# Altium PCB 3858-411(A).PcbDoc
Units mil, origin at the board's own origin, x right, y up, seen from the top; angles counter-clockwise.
Board outline 1549 x 1518 mil, 4 copper layers (Top Layer, Internal Plane 1, Mid-Layer 1, Bottom Layer); 62 components, 38 nets, 245 pads, 476 vias.
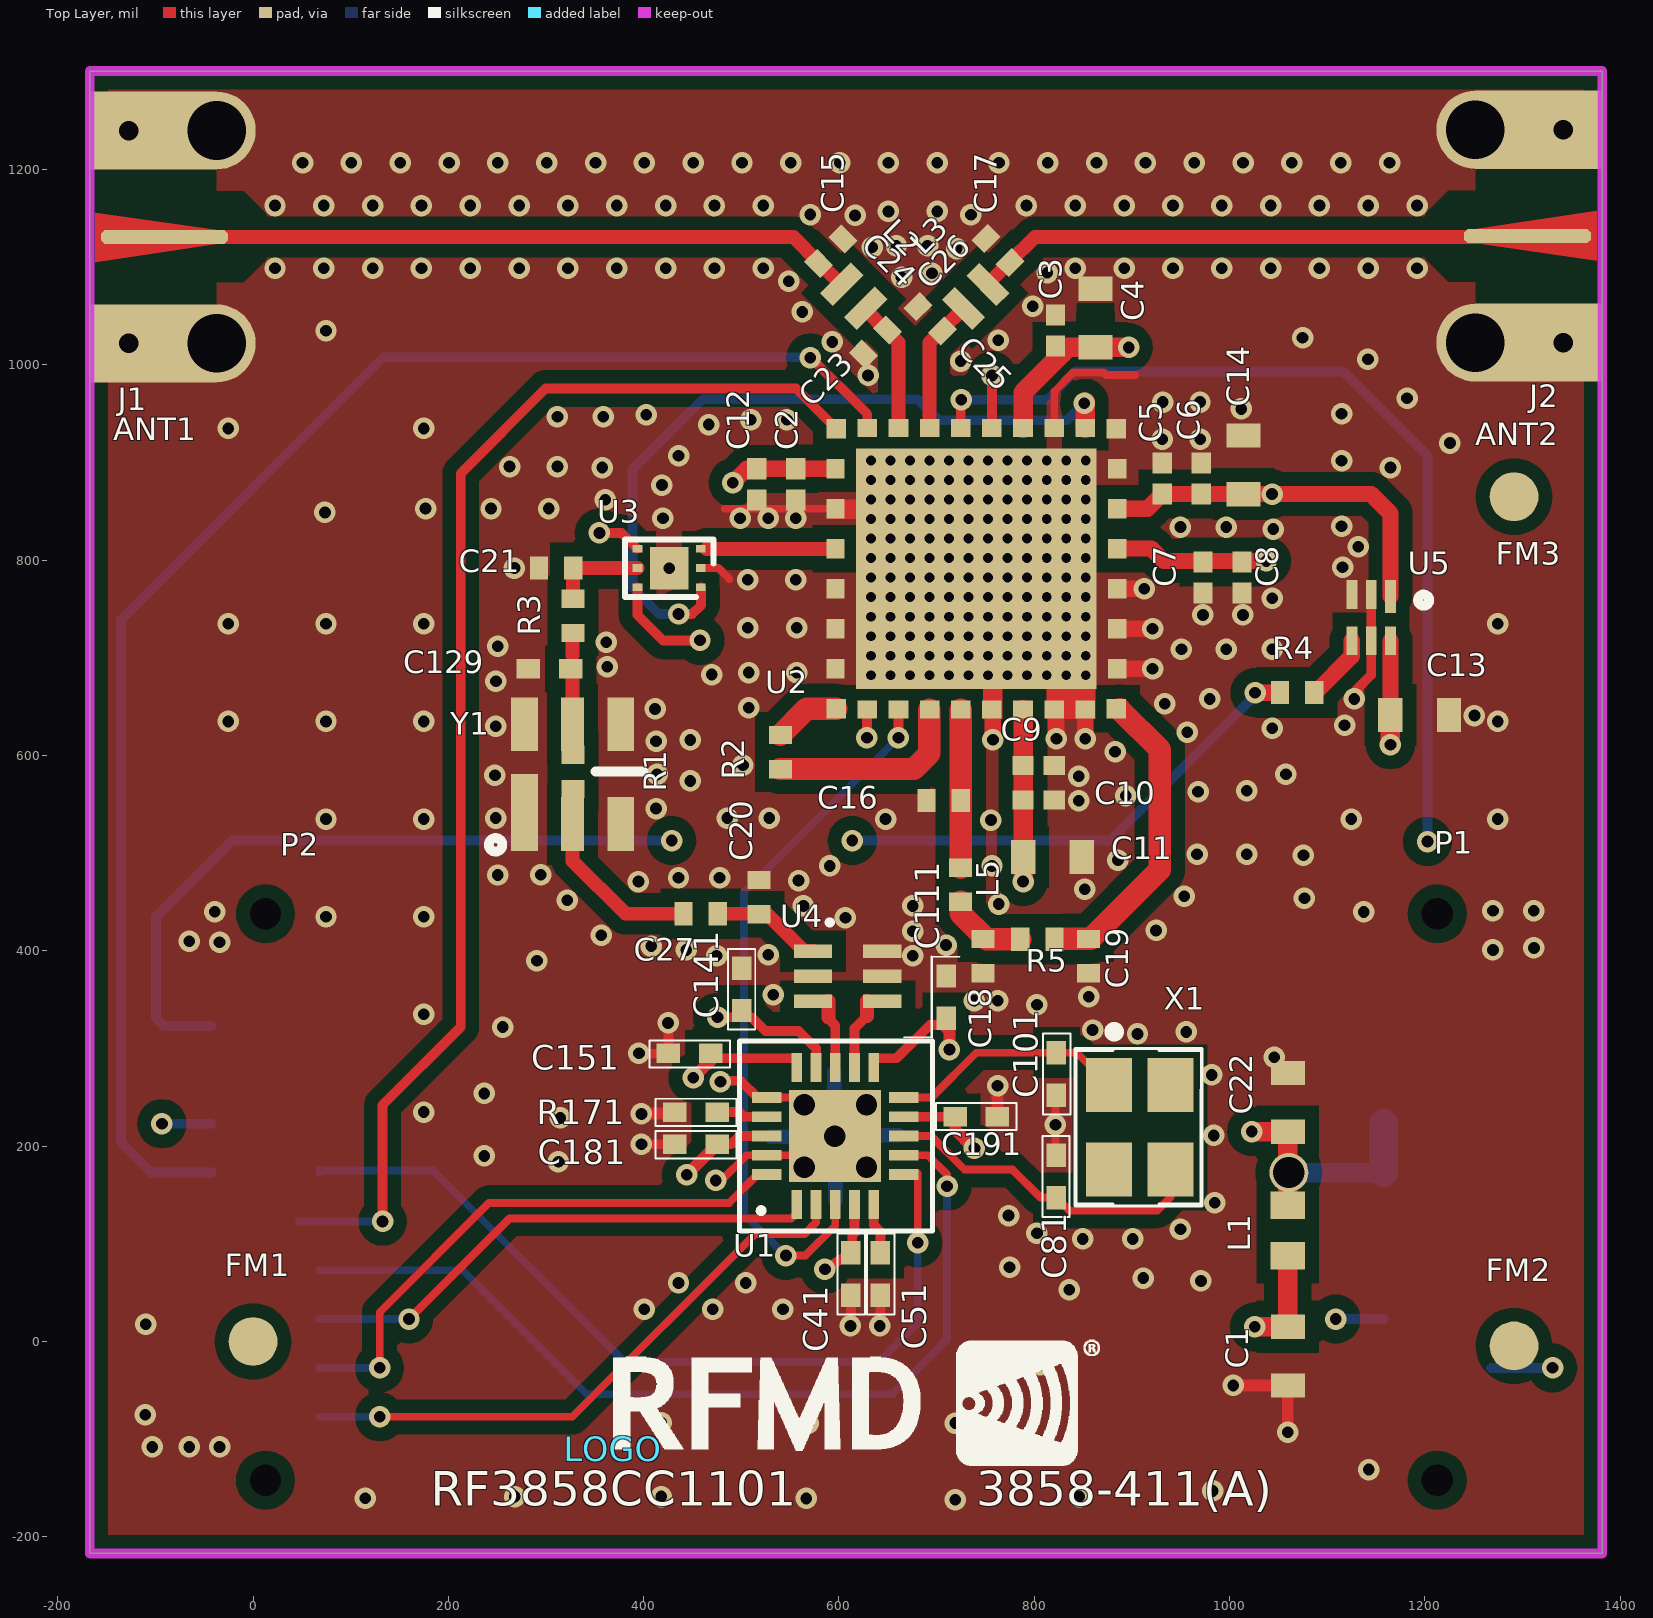
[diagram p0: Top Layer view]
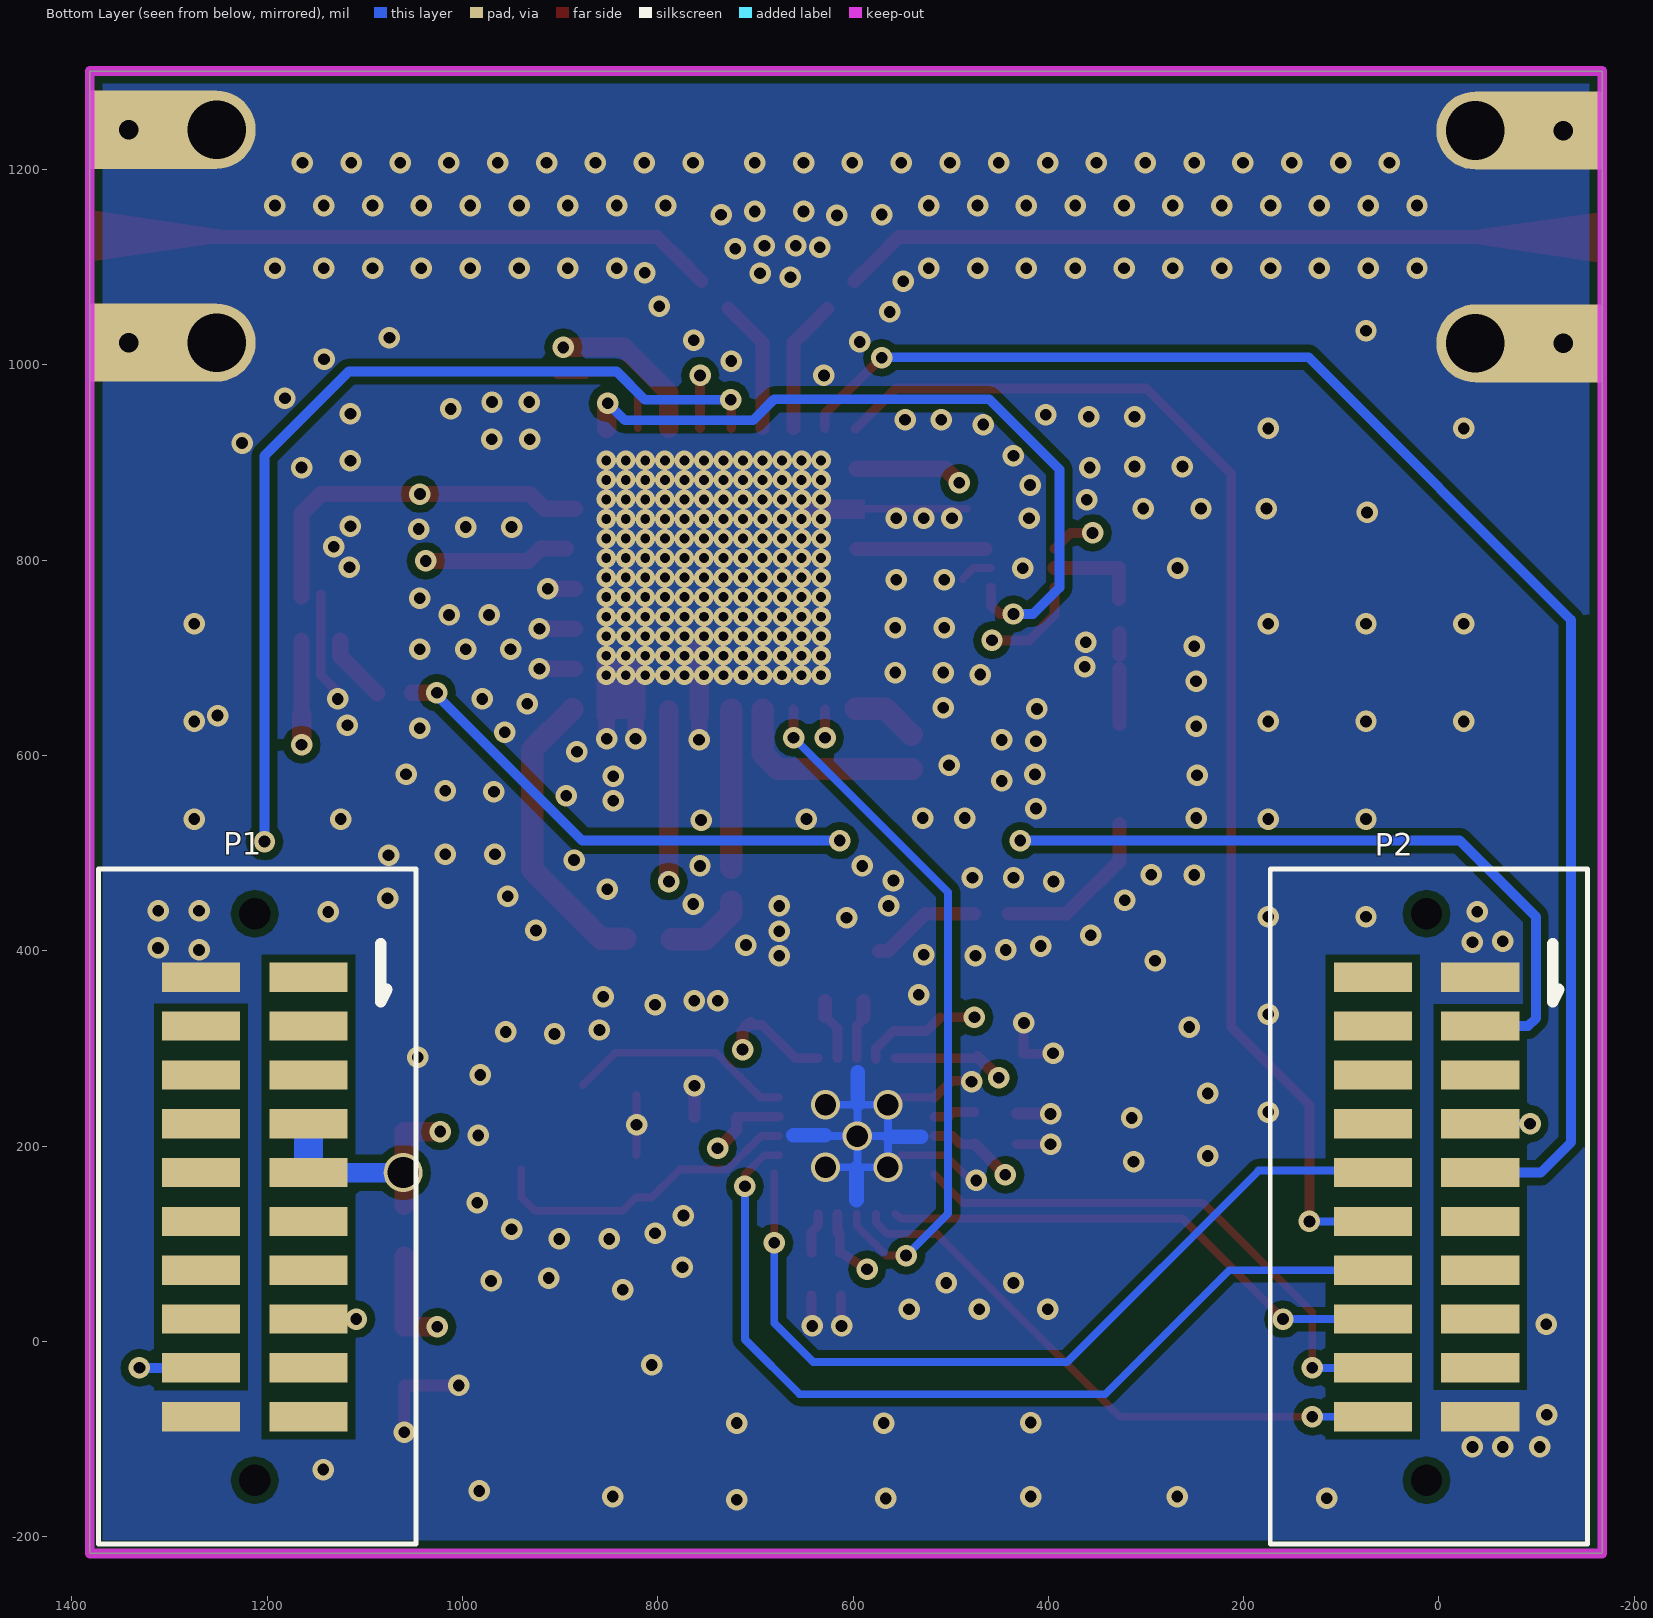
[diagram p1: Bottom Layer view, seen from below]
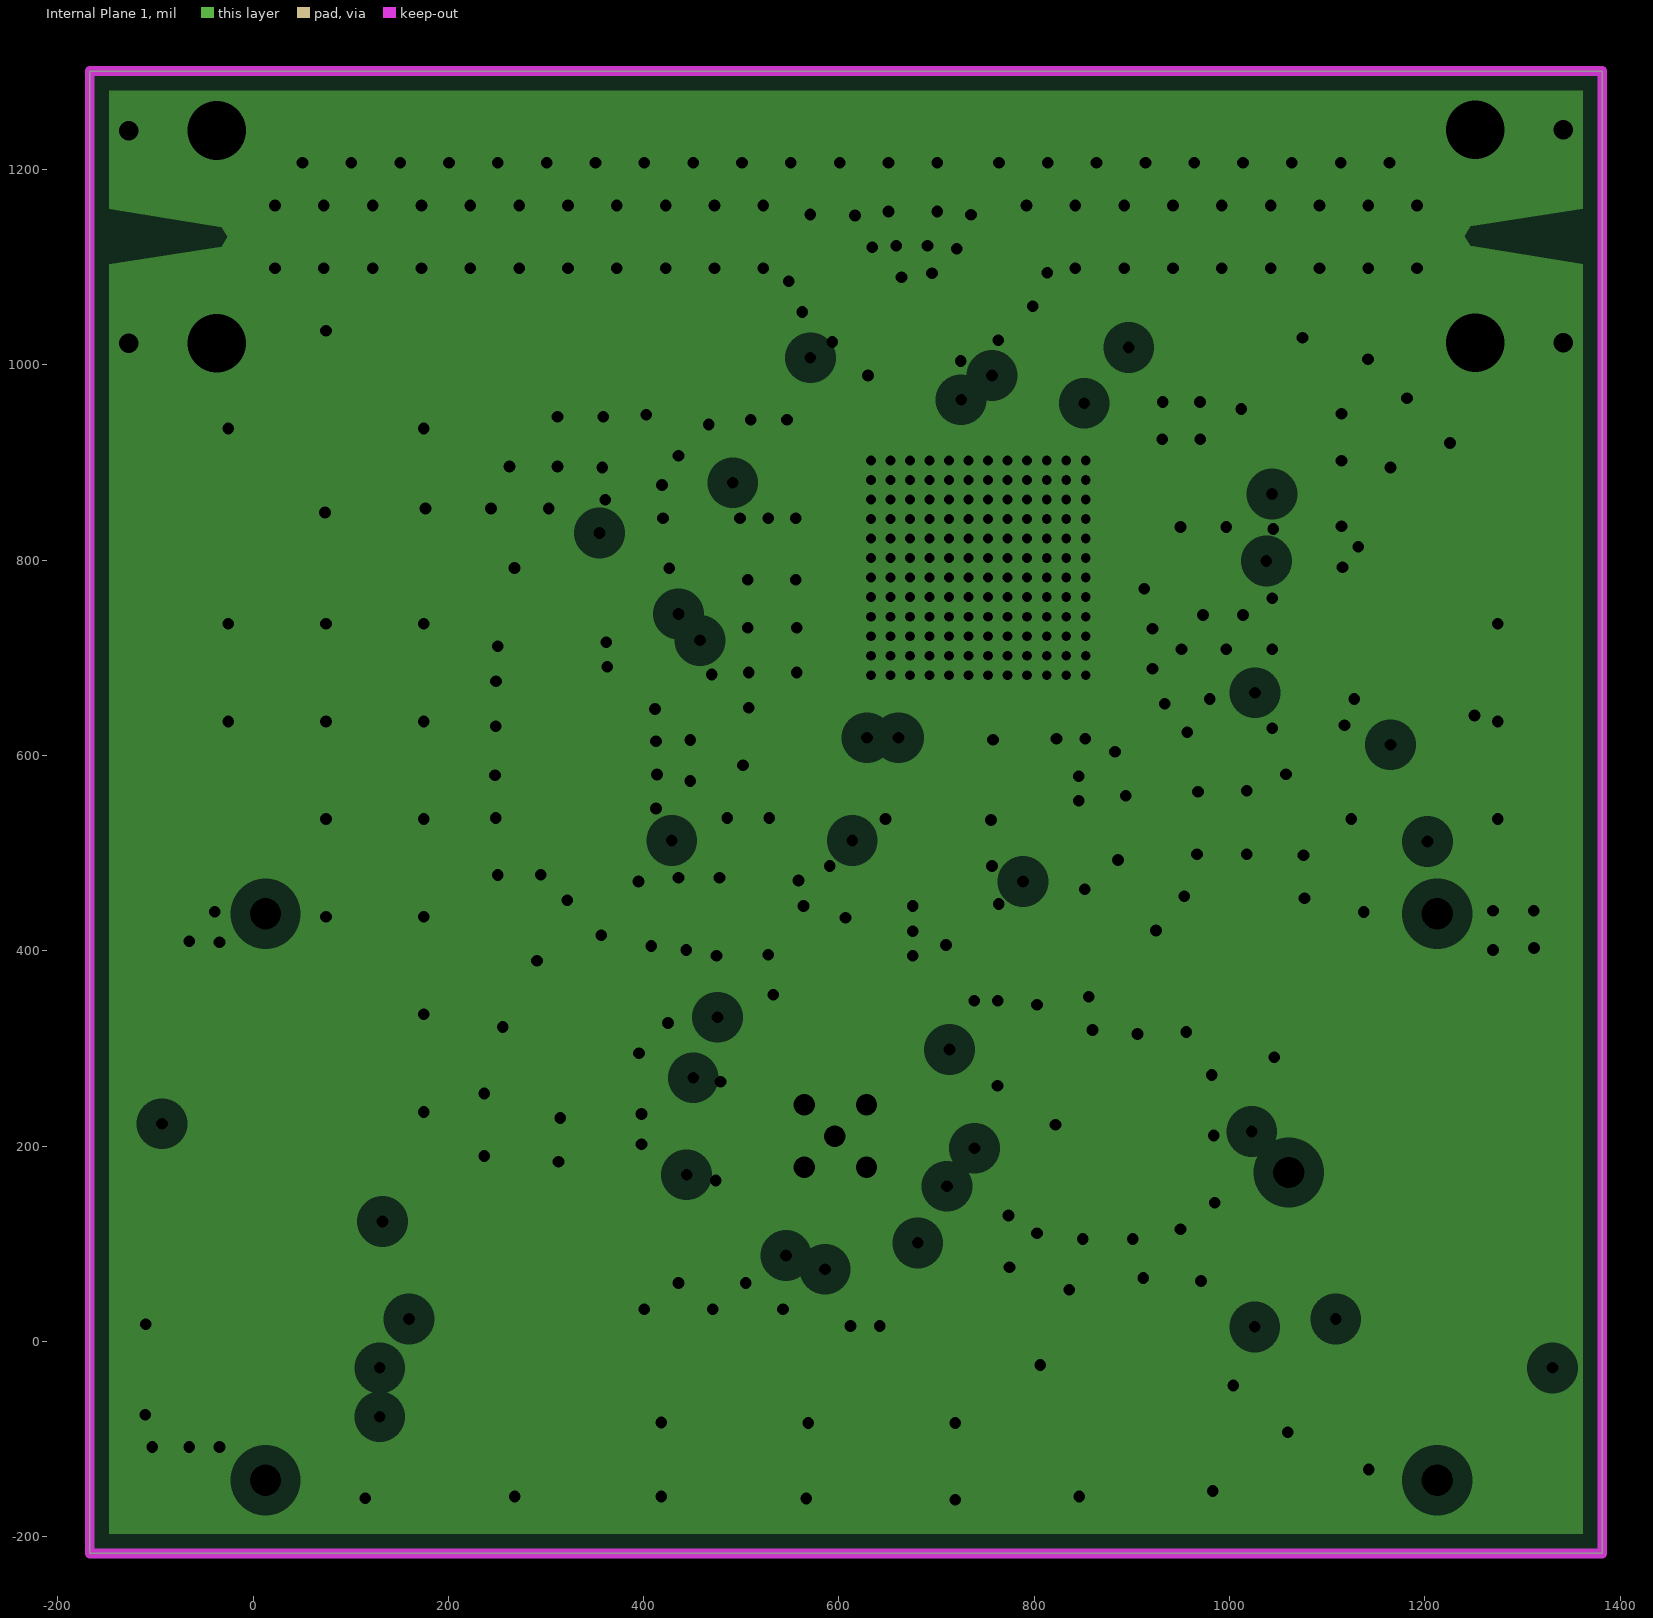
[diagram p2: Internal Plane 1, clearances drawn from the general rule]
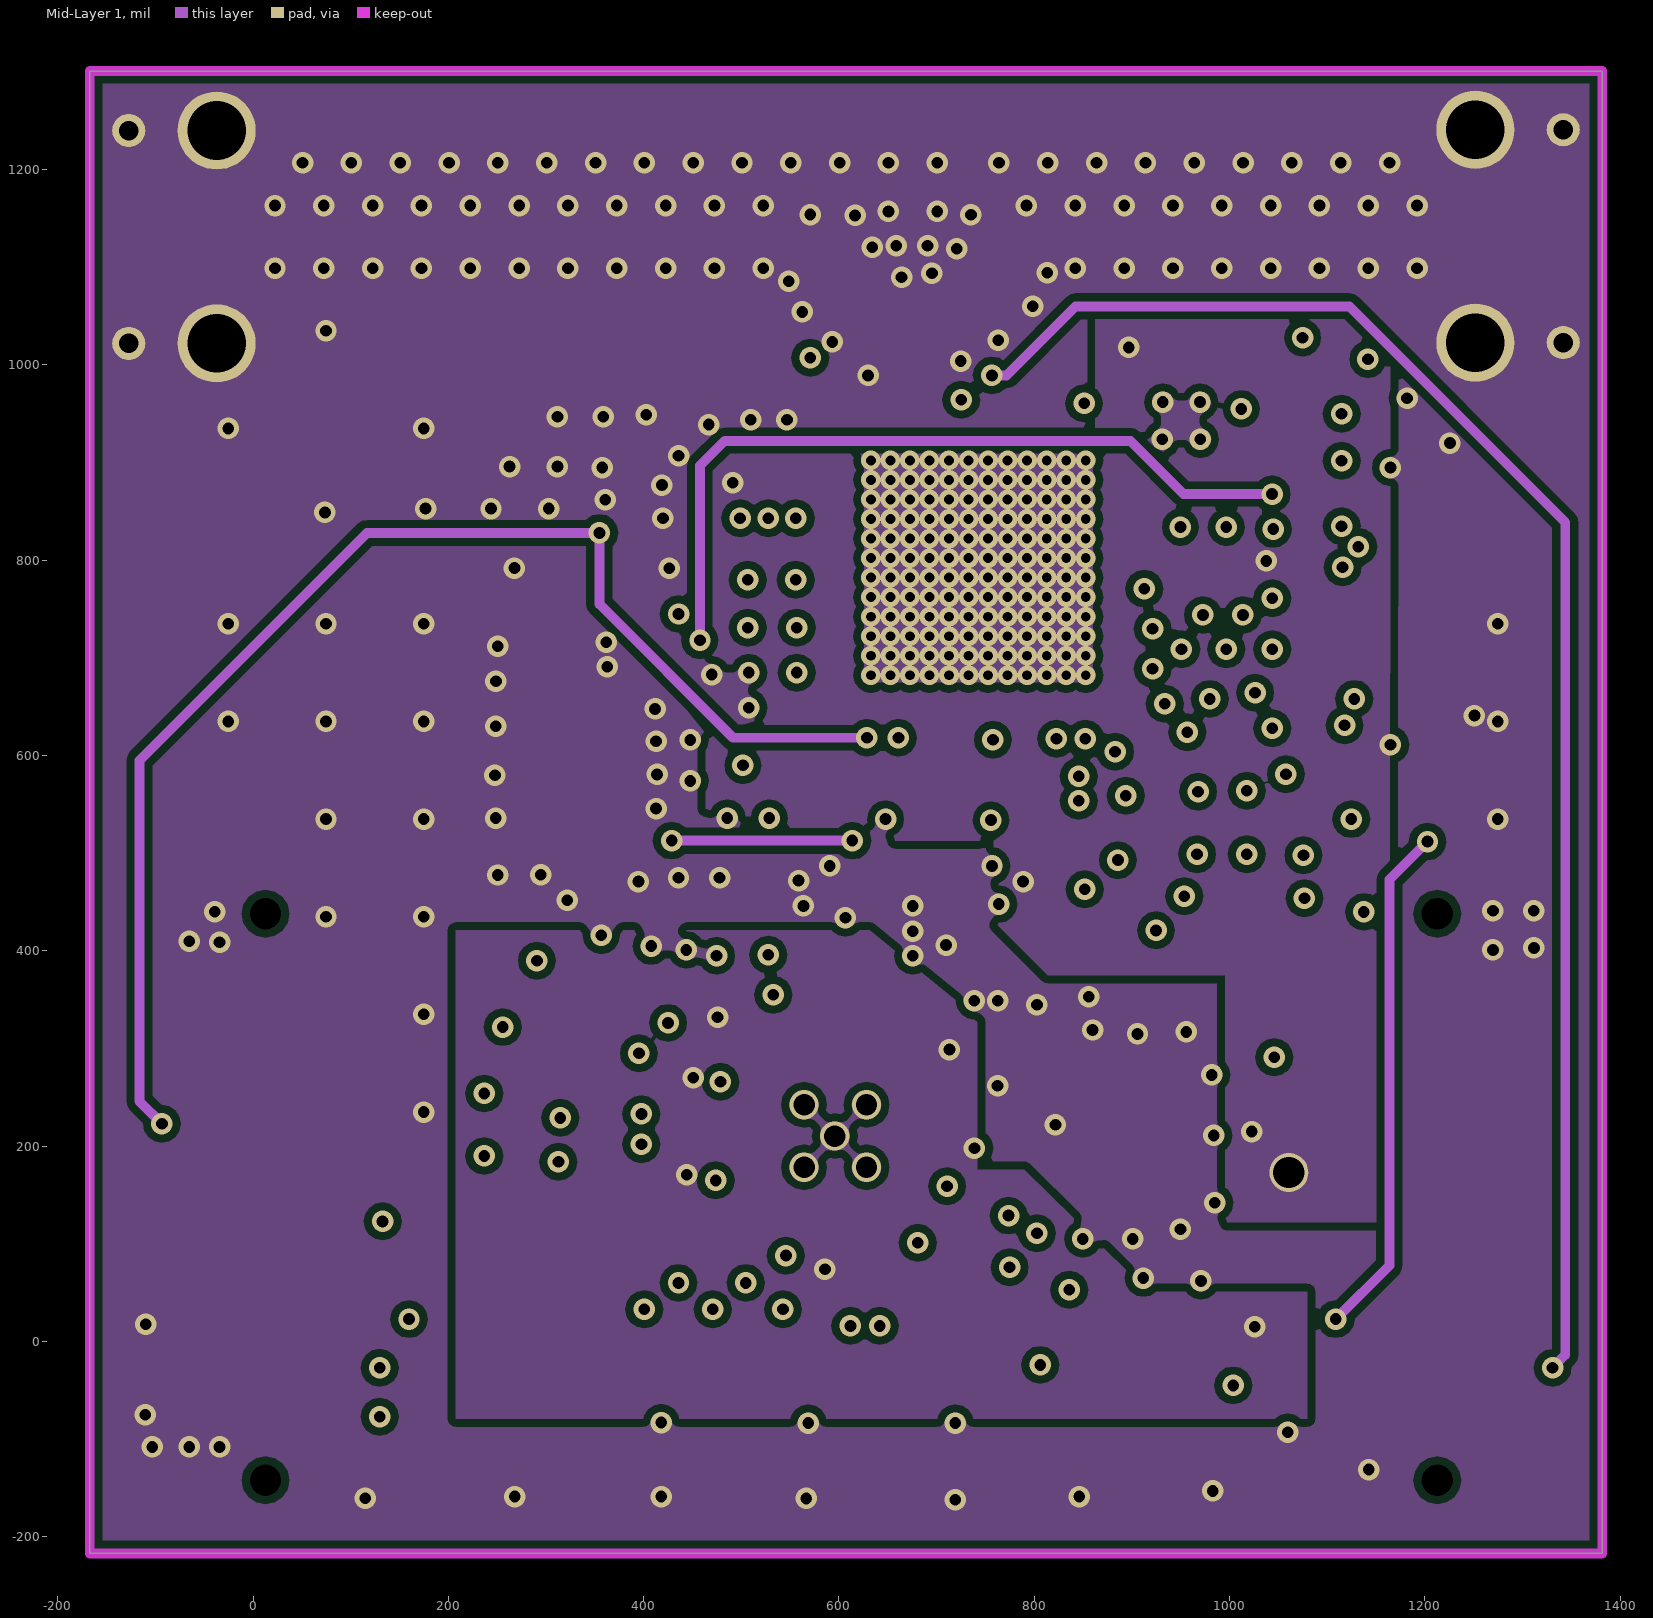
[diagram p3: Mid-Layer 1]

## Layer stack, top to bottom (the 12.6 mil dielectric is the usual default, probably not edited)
Top Layer: signal copper 1.4
Dielectric: core 12.6, FR-4, Dk 4.8
Internal Plane 1: plane copper 1.4, net GND
Dielectric: prepreg 12.6, FR-4, Dk 4.8
Mid-Layer 1: signal copper 1.4
Dielectric: core 12.6, FR-4, Dk 4.8
Bottom Layer: signal copper 1.4

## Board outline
-167.3,-217 1381.7,-217 1381.7,1301 -167.3,1301

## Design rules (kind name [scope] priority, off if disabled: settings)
Clearance Clearance_2 [((InPoly)) And InNet('GND') or (IsVia or IsPad) vs HasFootprintPad('SMA_008_MABDC_GP1_VIPER','1')] p1: gap=40
Clearance Clearance_1 [((InPoly)) AND InNet('GND') and OnLayer('Top Layer')] p2: gap=14
Clearance Clearance_3 [InPoly and (OnLayer('Mid-Layer 1') or OnLayer('Bottom Layer'))] p3: gap=8
Clearance Connectors [IsTrack and IsKeepout vs HasFootprintPad('HDR_*','*') or (HasFootprint('SMA_008_MABDC_GP1_VIPER'))] p4: gap=0
Clearance [InPoly AND InNet('GND') And OnLayer('BottomLayer')] p5: gap=10
Clearance Clearance_4 [All] p6: gap=5
ComponentClearance [All] p1: gap=8 collisioncheckmode=3 verticalgap=10
HoleSize [All] p1: absolutevalues=TRUE maxlimit=125 minlimit=8 maxpercent=80.000 minpercent=20.000
PlaneClearance [All] p1: clearance=20
PlaneConnect [All] p1: planeconnectstyle=Direct reliefexpansion=20 reliefentries=4 reliefconductorwidth=10 reliefairgap=10
PolygonConnect [All] p1: connectstyle=Direct reliefconductorwidth=10 reliefentries=4 polygonreliefangle="90 Angle"
RoutingLayers [All] p1: top layer_v5=TRUE mid layer 1_v5=FALSE bottom layer_v5=TRUE
RoutingVias [All] p1: holewidth=8 width=20 viastyle="Through Hole" minholewidth=8 minwidth=20 maxholewidth=28 maxwidth=50
ShortCircuit [IsKeepOut vs HasFootprintPad('SMA_008_MABDC_G1_VIPER','*') Or HasFootprintPad('HDR_*','*') or (IsPolygon and OnTopLayer)] p1: allowed=TRUE
SolderMaskExpansion [All] p1: expansion=4
TestPointUsage [All] p1: valid=0 allowmultiple=FALSE
Testpoint [(IsPad And (OnTopLayer Or OnBottomLayer))] p1: side=3 testpointundercomponent=TRUE minsize=40 maxsize=100 preferedsize=60 minholesize=20 maxholesize=40 preferedholesize=32 testpointgrid=1 style=297 order=0-112345678
Width [All] p1: maxlimit=100 minlimit=5 preferedwidth=14.25
13 further rules are at their usual default settings.

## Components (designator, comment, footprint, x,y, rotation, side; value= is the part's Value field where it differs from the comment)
C1 "1uF" 0603(A)#1 1059.7,-15 r270 top
C2 "62pF" 0402(A)#1 555.7,877.78 r270 top
C3 "0.1uF" 0402(A)#1 821.8,1035.25 r270 top
C4 "10uF" 0603(A)#2 862.7,1048 r90 top
C5 "62pF" 0402(A)#2 931.03,883.78 r270 top
C6 "DNI" 0402(A)#3 971.03,883.78 r90 top
C7 "68pF" 0402(A)#3 972.67,782.28 r270 top
C8 "0.1uF" 0402(A)#2 1012.67,782.28 r90 top
C9 "68pF" 0402(A)#3 804.45,590 r0 top
C10 "0.1uF" 0402(A)#2 804.45,554.64 r180 top
C11 "10uF" 0603(A)#3 818.5,496 r180 top
C12 "1uF" 0402(A)#1 515.7,877.78 r90 top
C13 "1nF" 0603(A)#2 1194.73,641.6 r180 top
C14 "1uF" 0603(A)#2 1014.38,897.83 r270 top
C15 "3.6pF" 0402_S#1 579.12,1104.43 r45 top
C16 "1.5pF" 0402_S#2 689.83,554.44 r0 top
C17 "3.6pF" 0402_S#1 775.01,1104.61 r135 top
C18 "DNI" 0402_S#2 747.64,411.94 r270 top
C19 "DNI" 0402_S#2 855.82,411.94 r270 top
C20 "DNI" 0402_S#2 517.67,437.73 r90 top
C21 "DNI" 0402_S#2 327.67,791.73 r180 top
C22 "DNI" 0603(A)#1 1059.67,245 r90 top
C23 "3.6pF" 0402_S#1 649.81,1035.39 r225 top
C24 "0.2pF" 0402_S#1 619.85,1050.51 r135 top
C25 "3.6pF" 0402_S#1 705.48,1034.78 r135 top
C26 "0.2pF" 0402_S#1 734.65,1050.98 r45 top
C27 "100pF" 0402_S#2 475.67,437.73 r180 top
C41 "100nF" 0402_TI#1 612.3,90.8 r270 top
C51 "100nF" 0402_TI#1 642.5,90.8 r270 top
C81 "12pF" 0402_TI#1 822.7,147.4 r90 top
C101 "15pF" 0402_TI#1 822.7,295.7 r270 top
C111 "100nF" 0402_TI#1 709.67,331 r90 top
C129 "CAPACITOR(A)" 0402_TI#2 325.3,688.73 r180 top
C141 "100nF" 0402_TI#1 500.67,339 r90 top
C151 "100nF" 0402_TI#1 468.67,295 r180 top
C181 "100nF" 0402_TI#1 475.3,202 r180 top
C191 "100nF" 0402_TI#2 719,230.1 r0 top
FM1 "FM" FM 0,0 r0 top
FM2 "FM" FM 1291.3,-4.5 r90 top
FM3 "FM" FM 1291.3,865.1 r90 top
J1 "ANT1" SMA_008_MABDC_GP1_VIPER -167.3,1131 r0 top locked
J2 "ANT2" SMA_008_MABDC_GP1_VIPER 1381.7,1132 r180 top locked
L1 "1Kohms" 0603_S 1059.7,87.4 r90 top
L2 "6.8nH" 0402_S#1 634.49,1065.29 r135 top
L3 "6.8nH" 0402_S#1 720.39,1065.25 r45 top
L5 "4.7nH (W/W Coilcraft 0402)" 0402_S#2 724.33,450.44 r90 top
LOGO "RFMDLOGO" RFMD_LOGO 368.7,-110 r0 top
P1 "HDR_2X10" 20PIN_CON 1157.7,-77 r0 top
P2 "HDR_2X10" 20PIN_CON -42.3,-77 r0 top
R1 "0ohm" 0402_S#2 327.3,566.01 r90 top
R2 "0ohm" 0402_S#2 539.67,586.28 r90 top
R3 "0ohm" 0402_S#2 327.3,725.73 r90 top
R4 "0ohm" 0402_S#2 1051.86,664.77 r0 top
R5 "0OHM" 0402_S#2 820.48,411.6 r180 top
R171 "56K" 0402_TI#1 475.3,235 r180 top
U1 "CC1101" CC1101 595.8,210.4 r0 top locked
U2 "RF3858" RF3858B 740.67,791.28 r90 top
U3 "RF1126" 1126 426.19,791.87 r180 top
U4 "0896BM15A0001" "JOHANSON 896MHz" 608.87,374.12 r90 top
U5 "2.85V" TPS727XX 1145.04,741.22 r270 top
X1 "26.0MHz (NX3225GA)" Crystal 908.2,219.3 r0 top
Y1 "915.00MHz" "SAW EPCOS B3588" 327.3,581.01 r90 top

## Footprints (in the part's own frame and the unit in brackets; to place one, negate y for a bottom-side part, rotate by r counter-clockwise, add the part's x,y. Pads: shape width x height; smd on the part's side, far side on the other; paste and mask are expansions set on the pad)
20PIN_CON [mil]
  rect 80x30 smd far side paste-40 mask+2: 1(0,450) 2(110,450) 3(0,400) 4(110,400) 5(0,350) 6(110,350) 7(0,300) 8(110,300) 9(0,250) 10(110,250) 11(0,200) 12(110,200) 13(0,150) 14(110,150) 15(0,100) 16(110,100) 17(0,50) 18(110,50) 19(0,0) 20(110,0)
  round 5 hole 32 mask+31.5: 21(55,-65) 22(55,515)
0402(A)#1 [mm]
  rect 0.55x0.5 smd mask+0.074: 1(-0.405,0) 2(0.405,0)
0402(A)#2 [mm]
  rect 0.55x0.5 smd mask+0.051: 1(-0.405,0)
  rect 0.55x0.5 smd mask+0.074: 2(0.405,0)
0402(A)#3 [mm]
  rect 0.55x0.5 smd mask+0.074: 1(-0.405,0)
  rect 0.55x0.5 smd mask+0.051: 2(0.405,0)
0402_S#1 [mm]
  rect 0.475x0.6 smd mask+0.076: 1(-0.004,-0.009) 2(0.885,-0.009)
0402_S#2 [mm]
  rect 0.475x0.6 smd: 1(-0.004,-0.009) 2(0.885,-0.009)
0402_TI#1 [mil]
  rect 24x20 smd paste+0 mask+2: 1(0,0) 2(43.3,0)
0402_TI#2 [mil]
  rect 24x20 smd: 1(0,0) 2(43.3,0)
0603(A)#1 [mil]
  rect 25x35 smd: 1(-30,0) 2(30,0)
0603(A)#2 [mil]
  rect 25x35 smd mask+3: 1(-30,0) 2(30,0)
0603(A)#3 [mil]
  rect 25x35 smd mask+2: 1(-30,0)
  rect 25x35 smd mask+3: 2(30,0)
0603_S [mm]
  rect 0.713x0.9 smd: 1(0.008,0) 2(1.329,0)
1126 [mm] "rev A"
  rect 0.25x0.2 smd: 1(-0.824,0.495) 2(-0.824,-0.005) 3(-0.824,-0.505) 4(0.826,-0.505) 5(0.826,-0.005) 6(0.826,0.495)
  rect 1x1.1 smd: 7(0,0)
  round 0.4 on Top Overlay: ""(-1.257,0.292)
  silkscreen extent -1.15,-0.75 1.15,0.75
CC1101 [mil]
  rect 11x29.99 smd: 1(-39,-70.1) 2(-19.3,-70.1) 3(0.4,-70.1) 4(20,-70.1) 5(39.7,-70.1)
  rect 30x11 smd: 6(70.6,-39.4) 7(70.6,-19.7) 8(70.6,0) 9(70.6,19.7) 10(70.6,39.4)
  rect 11x30 smd: 11(39.7,70.2) 12(20,70.2) 13(0.4,70.2) 14(-19.3,70.2) 15(-39,70.2)
  rect 29.99x11 smd: 16(-69.9,39.4) 17(-69.9,19.7) 18(-69.9,0) 19(-69.9,-19.7) 20(-69.9,-39.4)
  rect 94x94 smd: 21(0,0)
  silkscreen extent -98,-97 100,97
Crystal [mil] "NDK"
  rect 47.2x55.1 smd paste-1.15 mask+3: 1(31.5,-43.3) 2(-31.5,43.3) 3(-31.5,-43.3) 4(31.5,43.3)
  silkscreen extent -66,-80 64,81
FM [mil]
  round 50 smd paste+0 mask+9: 1(0,0)
"JOHANSON 896MHz" [mm]
  rect 0.35x1 smd: 1(0.65,0.9) 2(0,0.9) 3(-0.65,0.9) 4(-0.65,-0.9) 5(0,-0.9) 6(0.65,-0.9)
RF3858B [mm]
  rect 0.51x0.51 smd: 1(-3.64,3.64) 10(-3.64,-3.64) 17(3.64,-3.64) 26(3.64,3.64)
  rect 0.475x0.51 smd: 2(-3.662,2.835) 3(-3.662,2.025) 4(-3.662,1.215) 5(-3.662,0.405) 6(-3.662,-0.405) 7(-3.662,-1.215) 8(-3.662,-2.025) 9(-3.662,-2.835) 18(3.662,-2.835) 19(3.662,-2.025) 20(3.662,-1.215) 21(3.662,-0.405) 22(3.662,0.405) 23(3.662,1.215) 24(3.662,2.025) 25(3.662,2.835)
  rect 0.51x0.475 smd: 11(-2.602,-3.662) 12(-1.561,-3.662) 13(-0.52,-3.662) 14(0.521,-3.662) 15(1.562,-3.662) 16(2.603,-3.662) 27(2.602,3.662) 28(1.561,3.662) 29(0.52,3.662) 30(-0.521,3.662) 31(-1.562,3.662) 32(-2.603,3.663)
  rect 6.25x6.25 smd: 33(0,0)
RFMD_LOGO [mil]
  silkscreen extent 0,-17 499,112
"SAW EPCOS B3588" [mm]
  rect 2x0.7 smd: 1(-1,1.25)
  rect 1.4x0.6 smd: 2(-1.3,0) 5(1.3,0)
  rect 1.4x0.7 smd: 3(-1.3,-1.25) 4(1.3,-1.25) 6(1.3,1.25)
SMA_008_MABDC_GP1_VIPER [mil]
  oct 130x14.25 smd: 1(76.5,0.1)
  rect 130x80 smd: 2(65,109.1) 6(65,-108.9)
  rect 130x80 smd far side: 3(65,109.1) 7(65,-108.9)
  round 34 hole 20: 4(40,109.1) 8(40,-108.9)
  round 80 hole 60: 5(130,109.1) 9(130,-108.9)
  Top Layer pour cut-out: -1.44,-106.8 130,-108.9 130,109.1 -1.44,111.2
  Top Layer region: 132.7,-6.92 132.7,7.08 5.7,25.08 5.7,-25.92 131.7,-6.92
  Internal Plane 1 region: -0.3,-30.92 -0.3,32.08 134.7,10.08 140.7,0.08 134.7,-9.92
TPS727XX [mm] "TI- Linear Regulator"
  rect 0.85x0.28 smd mask+0.05: 1(-0.55,0.5)
  rect 0.75x0.28 smd mask+0.05: 2(-0.6,0) 3(-0.6,-0.5) 4(0.6,-0.5) 5(0.6,0) 6(0.6,0.5)

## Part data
C1 C2 C3 C4 C5 C6 C7 C8 C9 C10 C11 C12 C13 C14 C15 C16 C17 C18 C19 C20 C21 C22 C23 C24 C25 C26 C27 C41 C51 C81 C101 C111 C141 C151 C181 C191: library part CAPACITOR(A), "Capacitor"
C129: "Capacitor"
J1 J2: library part SMA_008, "SMA Connector"
L1 L2 L3 L5 R5: library part INDUCTOR(A), "Inductor"
LOGO: "RFMD LOGO"
R1 R2 R3 R4 R171: library part RESISTOR(A), "Resistor"
U1: library part PKG_20L, "PKG_20L"
U3: library part PKG_6L
U4: library part "BALUN JOHANSON"
U5 Y1: library part "SAW 6L", "SAW FILTER"
X1: library part CRYSTAL(A), "CRYSTAL"

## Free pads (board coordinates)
  round 25 on Top Overlay: 0(591.94,595.28)
  round 40 hole 32 mask-3: 1(1060.7,173)

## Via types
v1: diameter 22, hole 12, Top Layer to Bottom Layer, tented top, 177 vias
v2: diameter 22, hole 12, Top Layer to Bottom Layer, 150 vias
v3: diameter 20, hole 10, Top Layer to Bottom Layer, tented top, 144 vias
v4: diameter 30, hole 22, Top Layer to Bottom Layer, 5 vias

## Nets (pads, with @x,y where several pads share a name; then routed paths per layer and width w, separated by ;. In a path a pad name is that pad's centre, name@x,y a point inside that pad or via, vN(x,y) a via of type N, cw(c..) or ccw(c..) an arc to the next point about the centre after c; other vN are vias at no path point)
CSN: P2.14 U1.7 | length 930.7
  Top Layer w8: U1.7@675.9,190.7 691,190.7 710.7,171 v2(710.7,159)
  Bottom Layer w8: P2.14 214.67,73 341.67,-54 654.67,-54 710.7,2.03 v2(710.7,159)
GDO0: P2.10 U1.6 | length 865.7
  Top Layer w8: v2(680.7,101) U1.6@680.7,172
  Bottom Layer w8: P2.10 67.7,175 184.67,175 380.67,-21 640.67,-21 680.7,19.03 v2(680.7,101)
GND: C1.2 C2.2 C3.1 C4.2 C5.1 C6.2 C7.2 C8.1 C9.2 C10.1 C11.1 C12.1 C13.1 C14.1 C15.2 C16.1 C17.2 C18.2 C19.2 C20.2 C21.2 C22.2 C23.2 C25.2 C41.2 C51.2 C81.2 C101.2 C111.2 C129.2 C141.2 C151.2 C181.2 C191.2 J1.2 J1.3 J1.4 J1.5 J1.6 J1.7 J1.8 J1.9 J2.2 J2.3 J2.4 J2.5 J2.6 J2.7 J2.8 J2.9 P1.2 P1.20 P2.1 P2.19 R171.2 U1.16 U1.19 U1.21 U2.6 U2.8 U2.9 U2.11 U2.12 U2.13 U2.16 U2.17 U2.19 U2.28 U2.30 U2.31 U2.32 U2.33 U3.2 U3.7 U4.2 U4.5 U4.6 U5.2 U5.3 U5.5 Y1.1 Y1.3 Y1.4 Y1.6 | length 1592.4
  Top Layer w8: U3.2 476.63,792.07 487.7,781 ; v2(473.7,165) 479.7,165 505.4,190.7 U1.19 U1.21@550.4,190.7 ; 483.44,852.74 U2.28 ; U1.16@516.5,249.8 U1.16 U1.21@550.4,249.8 ; U2.19 820.39,972.69 839.98,992.28 870.95,992.28 873.65,989.59 903.11,989.59 ; C81.2@821.7,190.7 v2(821.7,222) C101.2@821.7,252.4
  Top Layer w10: v2(397.7,202) C181.2 ; v2@397.97,294.8 425.47,294.8 v2@425.47,322.3 ; v2@424.97,322.3 v2(424.97,326.2) ; v2(478.67,266) 479.67,267 499.3,267 U1.16@516.5,249.8 ; v2@612.3,16 C41.2 ; v2@642.5,16 C51.2 ; v1@1129.7,667 1145.04,682.34 U5.5 U5.2
  Top Layer w12: v2(397.7,233) v2@405.7,233 ; v2@405.7,233.4 R171.2@432,233.4 ; C191.2@762.3,230 v2@762.3,255.2 ; v2@762.4,255.1 v2(762.4,262) ; v2(1003.7,-45) C1.2 v2(1059.7,-93) ; v2@1142.1,-130.6 v2@1144.7,-127.9
  Top Layer w17: v1(757.67,616.28) U2.6@757.67,646.03 ; U2.8 822.67,644.81 v1(822.67,617.28) ; v1(852.28,617.28) U2.9 ; U2.11 v1(921.11,688.84) ; U2.12 v1(921.11,729.83) ; U2.13 v1(912.7,770.81)
  Bottom Layer w8: 595.3,179.4 v4@595.3,210.4 ; v4(595.8,210.4) 627.97,210.4 ; v4(628.2,178.4) 564.22,178.4 564.2,210.4 ; v4(628.2,242.4) 595.3,242.4 ; 564.2,210.4 v4@595.3,210.4 ; 564.2,210.4 v4(564.2,242.4) 595.3,242.4 ; v4@595.3,210.4 595.3,242.4
  Bottom Layer w12: v2@268,-163.1 v2(268,-158.8) ; v2@716.1,-83.3 v2@719.2,-83.3 ; v2@806.44,-23.54 v2@808.3,-25.3 ; v2@846.1,-163.1 v2(846.1,-158.8)
  Bottom Layer w15: 530.3,209.7 562.93,209.7 ; 595.1,243.27 595.1,275.9 ; 596.5,144.9 596.5,177.53 ; 628.67,211.1 661.3,211.1
  other v1: 900.7,105 802.7,111 174.7,235 981.7,273 905.7,315 859.7,319 174.7,335 762.7,349 855.7,353 532.67,355 474.67,395 675.67,395 1269.7,401 1311.7,403 407.67,405 675.67,420 924.67,421 606.67,434 74.7,435 174.7,435 1269.7,441 563.67,446 763.7,448 321.67,452 953.67,456 851.67,463 394.67,471 558.67,472 435.67,475 477.67,475 250.7,477.73 294.67,478 590.67,487 756.7,487 885.67,493 1075.67,498 966.67,499 1017.67,499 755.67,534 74.7,535 174.7,535 647.7,535 1124.7,535 1274.7,535 248.67,536 485.7,536 528.7,536 412.7,545.73 845.53,553.72 893.7,559 967.7,563 1017.7,564 447.7,574 845.53,578.72 247.67,580 413.7,580.73 1057.7,581 501.7,590 882.7,604 412.7,614.73 447.7,616 956.7,624 1043.7,628 248.67,630 1117.7,631 -25.3,635 74.7,635 174.7,635 1274.7,635 1250.7,641 411.7,647.73 507.7,649 933.7,653 979.7,658 1127.7,658 248.7,676 469.7,683 507.7,685 556.7,685 362.7,691 950.7,709 996.7,709 1043.7,709 250.7,712 361.7,716 506.7,731 556.7,731 -25.3,735 74.7,735 174.7,735 1274.7,735 972.7,744 1013.7,744 1043.7,761 506.7,780 555.7,780 267.67,792 426.19,791.87 1115.7,793 1131.7,814 1044.7,832 949.7,834 996.7,834 1114.7,835 419.7,843 498.7,843 527.7,843 555.7,843 73.67,849 176.67,853 243.67,853 302.67,853 360.67,862 418.7,877 357.7,895 1164.7,895 262.7,896 311.7,896 1114.7,902 435.7,907 1225.7,920 931.06,924 970.06,924 -25.3,935 174.7,935 466.7,939 509.7,944 546.7,944 311.7,947 358.7,947 402.7,949 1114.7,950 1012.06,955 931.7,962 969.7,962 1181.7,966 629.8,989.3 724.7,1004 1141.7,1006 593.1,1023.6 763.1,1025.4 1074.7,1028 74.7,1035 562.5,1054.3 798.4,1060.2 664.1,1089.7 695.2,1093.8 720.6,1119 634.1,1120.6 616.49,1153.11 735.19,1153.81
  other v2: 719.2,-162 115,-160.6 566.6,-160.7 418,-158.8 982.7,-153 1142.6,-131.1 -103.3,-108 -65.3,-108 -34.3,-108 568.6,-83.5 719.2,-83.5 418,-83 -110.3,-75 806,-24 611.7,16 641.7,16 -109.9,17.7 400.67,33 470.67,33 542.67,33 835.7,53 435.67,60 504.67,60 970.7,62 911.7,65 774.7,76 849.7,105 949.7,115 773.7,129 984.7,142 312.7,184 236.7,190 983.7,211 314.67,229 236.7,254 1045.7,291 395.17,295.1 955.7,317 255.7,322 802.7,345 738.67,349 290.7,390 527.67,396 443.67,401 709.67,406 -34.3,409 -65.3,410 356.67,416 -39.3,440 1137.5,439.9 1311.6,441.1 675.67,446 1076.7,454 548.6,1085.7 813.4,1094.4 22.48,1098.98 72.48,1098.98 122.48,1098.98 172.48,1098.98 222.48,1098.98 272.48,1098.98 322.48,1098.98 372.48,1098.98 422.48,1098.98 472.48,1098.98 522.48,1098.98 842.02,1098.98 892.02,1098.98 942.02,1098.98 992.02,1098.98 1042.02,1098.98 1092.02,1098.98 1142.02,1098.98 1192.02,1098.98 658.8,1122.1 690.7,1122.1 570.7,1154 650.7,1157.2 700.7,1157.2 22.48,1163.23 72.48,1163.23 122.48,1163.23 172.48,1163.23 222.48,1163.23 272.48,1163.23 322.48,1163.23 372.48,1163.23 422.48,1163.23 472.48,1163.23 522.48,1163.23 792.02,1163.23 842.02,1163.23 892.02,1163.23 942.02,1163.23 992.02,1163.23 1042.02,1163.23 1092.02,1163.23 1142.02,1163.23 1192.02,1163.23 50.7,1207.2 100.7,1207.2 150.7,1207.2 200.7,1207.2 250.7,1207.2 300.7,1207.2 350.7,1207.2 400.7,1207.2 450.7,1207.2 500.7,1207.2 550.7,1207.2 600.7,1207.2 650.7,1207.2 700.7,1207.2 763.8,1207.2 813.8,1207.2 863.8,1207.2 913.8,1207.2 963.8,1207.2 1013.8,1207.2 1063.8,1207.2 1113.8,1207.2 1163.8,1207.2
  other v3: 632.67,682.28 652.67,682.28 672.67,682.28 692.67,682.28 712.67,682.28 732.67,682.28 752.67,682.28 772.67,682.28 792.67,682.28 812.67,682.28 832.67,682.28 852.67,682.28 632.67,702.28 652.67,702.28 672.67,702.28 692.67,702.28 712.67,702.28 732.67,702.28 752.67,702.28 772.67,702.28 792.67,702.28 812.67,702.28 832.67,702.28 852.67,702.28 632.67,722.28 652.67,722.28 672.67,722.28 692.67,722.28 712.67,722.28 732.67,722.28 752.67,722.28 772.67,722.28 792.67,722.28 812.67,722.28 832.67,722.28 852.67,722.28 632.67,742.28 652.67,742.28 672.67,742.28 692.67,742.28 712.67,742.28 732.67,742.28 752.67,742.28 772.67,742.28 792.67,742.28 812.67,742.28 832.67,742.28 852.67,742.28 632.67,762.28 652.67,762.28 672.67,762.28 692.67,762.28 712.67,762.28 732.67,762.28 752.67,762.28 772.67,762.28 792.67,762.28 812.67,762.28 832.67,762.28 852.67,762.28 632.67,782.28 652.67,782.28 672.67,782.28 692.67,782.28 712.67,782.28 732.67,782.28 752.67,782.28 772.67,782.28 792.67,782.28 812.67,782.28 832.67,782.28 852.67,782.28 632.67,802.28 652.67,802.28 672.67,802.28 692.67,802.28 712.67,802.28 732.67,802.28 752.67,802.28 772.67,802.28 792.67,802.28 812.67,802.28 832.67,802.28 852.67,802.28 632.67,822.28 652.67,822.28 672.67,822.28 692.67,822.28 712.67,822.28 732.67,822.28 752.67,822.28 772.67,822.28 792.67,822.28 812.67,822.28 832.67,822.28 852.67,822.28 632.67,842.28 652.67,842.28 672.67,842.28 692.67,842.28 712.67,842.28 732.67,842.28 752.67,842.28 772.67,842.28 792.67,842.28 812.67,842.28 832.67,842.28 852.67,842.28 632.67,862.28 652.67,862.28 672.67,862.28 692.67,862.28 712.67,862.28 732.67,862.28 752.67,862.28 772.67,862.28 792.67,862.28 812.67,862.28 832.67,862.28 852.67,862.28 632.67,882.28 652.67,882.28 672.67,882.28 692.67,882.28 712.67,882.28 732.67,882.28 752.67,882.28 772.67,882.28 792.67,882.28 812.67,882.28 832.67,882.28 852.67,882.28 632.67,902.28 652.67,902.28 672.67,902.28 692.67,902.28 712.67,902.28 732.67,902.28 752.67,902.28 772.67,902.28 792.67,902.28 812.67,902.28 832.67,902.28 852.67,902.28
  other v4: 564.2,178.4
LNA_SEL: U1.3 U2.3 | length 717.9
  Top Layer w8: v1(545.67,88) 565.6,88 596.2,118.6 U1.3@596.2,130.8
  Top Layer w10: v1(660.94,618.27) U2.3
  Bottom Layer w8: v1(545.67,88) 502.67,131 502.67,460 v1(660.94,618.27)
LNA_VREF: P2.7 U2.2 U3.4 | length 1478.2
  Top Layer w10: v1(354.67,828) 377.42,828 U3.4 ; v1(628.69,618.27) U2.2@628.69,647.09
  Mid-Layer 1 w10: v2(-93.3,223) -116.3,246 -116.3,595 116.7,828 v1(354.67,828) 354.67,755.03 491.43,618.27 v1(628.69,618.27)
  Bottom Layer w10: v2(-93.3,223) P2.7
NetC15_1: C15.1 C24.2 J1.1 L2.2 | length 707.5
  Top Layer w14.25: J1.1@-90.52,1131.1 553.23,1131.1 579.75,1104.58 L2.2@598.33,1086
NetC16_2: C16.2 L5.2 U2.5 | length 161.8
  Top Layer w23: L5.2 C16.2 U2.5@724.67,647.03
NetC17_1: C17.1 C26.2 J2.1 L3.2 | length 581.8
  Top Layer w14.25: L3.2@755.43,1085.83 774.85,1105.25 800.7,1131.1 1305.2,1131.1 J2.1@1318.49,1131.1
NetC18_1: C18.1 L5.1 R5.2 | length 83.8
  Top Layer w23: L5.1 724.67,438.42 751.14,411.94 R5.2
NetC19_1: C19.1 R5.1 U2.10 | length 305.8
  Top Layer w23: 833.17,412.6 857.98,412.6 928.67,483.28 928.67,606.09 U2.10@887.48,647.28
NetC20_1: C20.1 C27.1 U4.1 | length 105.9
  Top Layer w14.25: C27.1 C20.1@518.01,438.07 ; C20.1@525.6,438.07 563.96,399.71 U4.1
NetC21_1: C21.1 R3.2 U3.5 | length 97.4
  Top Layer w14.25: R3.2 327.83,760.75 C21.1 U3.5
NetC23_1: C23.1 C24.1 L2.1 U2.24 | length 135.9
  Top Layer w14.25: L2.1@626.64,1057.21 626.71,1057.14 648.89,1034.95 660.94,1022.9 U2.24
NetC25_1: C25.1 C26.1 L3.1 U2.23 | length 136.7
  Top Layer w14.25: U2.23@692.67,935.64 692.67,1023.07 705.18,1035.58 L3.1@727.5,1057.9
NetC27_2: C27.2 R1.1 Y1.2 | length 173.7
  Top Layer w14.25: Y1.2 327.3,491.93 381.16,438.07 C27.2
NetC51_1: C51.1 U1.5 | length 42.9
  Top Layer w10: U1.5@635.6,130.8 635.6,119.1 642.5,112.2 C51.1
NetC81_1: C81.1 U1.8 X1.1 | length 329.3
  Top Layer w8: U1.8@675.9,210.4 694.3,210.4 728.7,176 777.7,176 806.3,147.4 C81.1 836,134 925.7,134 939.7,148 X1.1
NetC101_1: C101.1 U1.10 X1.2 | length 233.5
  Top Layer w8: U1.10@675.9,249.8 694.7,249.8 740.6,295.7 C101.1 843.6,295.7 X1.2
NetC129_1: C129.1 R1.2 R3.1 Y1.5 | length 79.1
  Top Layer w14.25: Y1.5 C129.1@327.3,688.73 ; 327.3,703 R3.1@327.3,725.57
NetP2_3: P2.3 R4.1 | length 1411.9
  Top Layer w16.73: v1(1026.1,664.43) R4.1
  Mid-Layer 1 w10: v1(428.67,513) v2(613.67,513) ; v1@1026.1,661.7 v1(1026.1,664.43)
  Bottom Layer w10: P2.3 -91.3,323 -99.3,331 -99.3,435 -21.3,513 v1(428.67,513) ; v2(613.67,513) 877.4,513 v1@1026.1,661.7
NetR2_1: R2.1 U2.4 | length 204.3
  Top Layer w23: R2.1@539.67,586.28 676.67,586.28 692.67,602.28 U2.4@692.67,646.92
NetR2_2: R2.2 U2.1 | length 68.5
  Top Layer w23: R2.2 566.86,647.98 U2.1
NetR4_2: R4.2 U5.4 | length 85.2
  Top Layer w16.73: R4.2@1087.13,664 1124.93,701.8 ; U5.4@1124.93,717.6 1124.93,701.8 ; U5.4 1125.36,702.23 1124.93,701.8
NetR171_1: R171.1 U1.17 | length 41.9
  Top Layer w10: R171.1 497.5,235 501.7,230.8 ; 502.7,230 U1.17@516.5,230.1
NetU1_12: U1.12 U4.4 | length 63.7
  Top Layer w10: U1.12@615.9,290.1 615.9,320.7 628.6,333.4
  Top Layer w14.25: 628.6,333.4 U4.4@628.6,348.53
NetU1_13: U1.13 U4.3 | length 61.6
  Top Layer w10: 588.39,331.7 596.2,323.8 U1.13@596.2,290.1
  Top Layer w14.25: 589.1,331.7 U4.3@589.1,348.53
NetU2_29: U2.29 U3.3 | length 131.9
  Top Layer w14.25: 464.53,811.75 U2.29
PA_IN: U2.18 U3.1 | length 759
  Top Layer w10: v1(435.7,745) 449.7,745 458.63,753.93 U3.1
  Top Layer w20: U2.18 v1@852.28,961.9
  Bottom Layer w10: v1@435.46,745.24 435.23,745 415.7,745 388.7,772 388.7,893 460.7,965 680.7,965 702.4,943.3 833.68,943.3 v1(851.13,960.75)
PA_VREG: C5.2 C6.1 C14.2 U2.15 U3.6 U5.1 | length 1300
  Top Layer w10: U3.6 393.67,744.03 419.7,718 v1(457.7,718)
  Top Layer w16.73: U2.15 915.98,852.78 C5.2 ; 950.67,867.83 C5.2 ; U5.1 1164.73,847.92 1144.81,867.83 v1(1043.49,867.83) C14.2 C6.1 C5.2
  Mid-Layer 1 w10: v1(457.7,718) 457.7,897 482.98,922.28 898.42,922.28 952.87,867.83 v1(1043.49,867.83)
SCLK: P2.16 U1.1 | length 533.5
  Top Layer w8: v2(159.7,23) 262.7,126 551.1,126 U1.1@556.8,130.8
  Bottom Layer w8: P2.16 v2(159.7,23)
SI: P2.18 U1.20 | length 566.4
  Top Layer w8: v2@127.7,-27 v2(129.7,-27) 129.7,30.03 241.67,142 487.7,142 ; 487.6,142.1 U1.20@516.5,171.1
  Bottom Layer w8: P2.18 v2(129.7,-27)
SO: P2.20 U1.2 | length 602.1
  Top Layer w8: v2@131.7,-77 v2(129.7,-77) 326.95,-77 513.95,110 564.7,110 576.5,121.9 U1.2@576.5,130.8
  Bottom Layer w8: P2.20 v2(129.7,-77)
VDD: C1.1 C41.1 C111.1 C141.1 C151.1 C181.1 C191.1 L1.1 U1.4 U1.9 U1.11 U1.14 U1.15 U1.18 | length 702
  Top Layer w10: C151.1@470.8,290.1 471.1,290.1 U1.15@556.8,290.1 ; C181.1 489.7,202 498.1,210.4 U1.18@516.5,210.4 ; v2(475.67,332) C141.1@500.67,332 ; 510.67,332 524.67,318 558.7,318 576.7,300 U1.14@576.7,289.2 ; v2(585.67,74) C41.1 ; C41.1@613.7,90.8 613.7,111 615.9,111 U1.4@615.9,130.8 ; U1.11@635.6,290.1 659.1,290.1 693.19,324.04 707.39,324.01 709.65,324 C111.1@710.67,324 ; U1.9@675.9,230.1 C191.1
  Top Layer w12: v2(443.98,170.68) C181.1 ; v2(450.67,270) 463.7,283 ; 464,283 471.1,290.1 C151.1@472.33,291.33 ; C111.1@705.03,326.37 707.39,324.01 713.1,318.3 v2(713.1,299) ; C191.1@719,229 719,216.7 v2@737.7,198
  Top Layer w20: v2(1025.67,15) C1.1 L1.1@1059.7,87.4
  other v2: 738.7,198
VDDRF: C2.1 C3.2 C4.1 C7.1 C8.2 C9.1 C10.2 C11.2 C12.2 C13.2 C22.1 L1.2 P1.7 P1.9 pad.1 U2.7 U2.14 U2.20 U2.27 U5.6 | length 969.3
  Top Layer w16.73: v1(491.33,879.5) 491.2,879.5 491.27,879.57 505.42,893.72 C12.2 ; C12.2@513.7,893.72 C12.2 ; U2.27 C2.1 C12.2 ; U2.14@893.85,812.13 919.91,812.13 932.71,799.33 972.67,799.33 1012.67,799.33 v1(1037.67,799.33) ; C13.2 U5.6
  Top Layer w20: v1(788.5,471) C11.2 C10.2 C9.1 U2.7 ; U2.20 788.5,971.8 828.9,1012.2 834.7,1018 C4.1 v1(896.67,1018) ; v1(1022.67,215) C22.1 ; L1.2 1059.7,173 C22.1 ; v1(1164.73,611.08) C13.2
  Bottom Layer w20: v1(788.5,471) v1@789.5,472 ; pad.1 P1.9
  Bottom Layer w30: P1.9 P1.7
VRX1: P2.9 U2.25 | length 1554.9
  Top Layer w10: v1@571.01,1007.69 629.05,949.65 U2.25
  Bottom Layer w10: P2.9 -104.3,173 -135.3,204 -135.3,739 133.69,1007.99 570.71,1007.99 v1@571.01,1007.69
  other v1: 570.71,1007.39
VRX2: P2.12 U2.26 | length 1322.5
  Top Layer w10: v1(132.67,123) 132.67,242 212.7,322.03 212.7,889 299.7,976 555.95,976 U2.26
  Bottom Layer w8: P2.12@47.14,123 P2.12 v1(132.67,123)
VTX1: P1.15 U2.22 | length 1526.1
  Top Layer w10: U2.22 v1@724.72,964.3
  Mid-Layer 1 w10: v2(1108.7,23) 1163.67,77.97 1163.67,473 v2(1202.67,512)
  Bottom Layer w10: v1(725.09,964.3) 813,964.3 841.98,993.28 1116.42,993.28 1202.67,907.03 v2(1202.67,512) ; v2(1108.7,23) P1.15
VTX2: P1.18 U2.21 | length 1697.7
  Top Layer w10: U2.21 v1(756.61,989.28) v1@756.61,991.28
  Mid-Layer 1 w10: v1@756.98,989.28 771.48,989.28 842.2,1060 1122.7,1060 1343.7,839 1343.7,-14 v2(1330.7,-27)
  Bottom Layer w10: P1.18 v2(1330.7,-27)
pads on no net: FM1.1 FM2.1 FM3.1 P1.1 P1.3 P1.4 P1.5 P1.6 P1.8 P1.10 P1.11 P1.12 P1.13 P1.14 P1.16 P1.17 P1.19 P1.21 P1.22 P2.2 P2.4 P2.5 P2.6 P2.8 P2.11 P2.13 P2.15 P2.17 P2.21 P2.22 U3. X1.3 X1.4

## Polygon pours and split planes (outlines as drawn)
GND on Top Layer "Top Layer-No Net" (solid, remove dead copper, pour order 1000): -167.3,-217 1381.7,-217 1381.7,1301 -167.3,1301
VDD on Mid-Layer 1 "Mid-Layer 1-No Net" (solid, pour order 1000): 207.67,-79 207.67,421 631.67,421 741.67,331 741.67,176 789.67,176 916.3,51 1079.67,51 1079.67,-79
VDDRF on Mid-Layer 1 "Mid-Layer 1-No Net 1" (solid, pour order 1001): 1163.67,122 995.67,122 995.67,375 813.67,375 758.67,430 758.67,513 463.67,513 462.67,898 502.67,935 862.67,935 862.67,1050 1164.67,1050
GND on Mid-Layer 1 "Mid-Layer 1-No Net 2" (solid, remove dead copper, pour order 1002): -167.3,-217 -167.3,1301 1381.7,1301 1381.7,-217
GND on Bottom Layer "BottomLayer-GND" (solid, remove dead copper, pour order 1007): -167.3,-217 -167.3,1301 1381.7,1301 1381.7,-217
no net on Top Overlay (solid): 523.2,134.1 523.19,133.89 523.17,133.68 523.13,133.48 523.08,133.27 523.02,133.07 522.94,132.88 522.85,132.69 522.74,132.51 522.63,132.34 522.5,132.17 522.36,132.02 522.21,131.87 522.05,131.74 521.88,131.61 521.7,131.5 521.52,131.4 521.32,131.32 521.13,131.25 520.93,131.19 520.72,131.15 520.51,131.12 520.3,131.1 520.1,131.1 519.89,131.12 519.68,131.15 519.47,131.19 519.27,131.25 519.08,131.32 518.88,131.4 518.7,131.5 518.52,131.61 518.35,131.74 518.19,131.87 518.04,132.02 517.9,132.17 517.77,132.34 517.66,132.51 517.55,132.69 517.46,132.88 517.38,133.07 517.32,133.27 517.27,133.48 517.23,133.68 517.21,133.89 517.3,134.1 517.31,134.31 517.33,134.52 517.37,134.72 517.42,134.93 517.48,135.13 517.56,135.32 517.65,135.51 517.76,135.69 517.87,135.86 518,136.03 518.14,136.18 518.29,136.33 518.45,136.46 518.62,136.59 518.8,136.7 518.98,136.8 519.18,136.88 519.37,136.95 519.57,137.01 519.78,137.05 519.99,137.08 520.2,137.1 520.4,137.1 520.61,137.08 520.82,137.05 521.03,137.01 521.23,136.95 521.42,136.88 521.62,136.8 521.8,136.7 521.98,136.59 522.15,136.46 522.31,136.33 522.46,136.18 522.6,136.03 522.73,135.86 522.84,135.69 522.95,135.51 523.04,135.32 523.12,135.13 523.18,134.93 523.23,134.72 523.27,134.52 523.29,134.31
no net on Top Overlay (solid): 523.2,134.1 523.19,133.89 523.17,133.68 523.13,133.48 523.08,133.27 523.02,133.07 522.94,132.88 522.85,132.69 522.74,132.51 522.63,132.34 522.5,132.17 522.36,132.02 522.21,131.87 522.05,131.74 521.88,131.61 521.7,131.5 521.52,131.4 521.32,131.32 521.13,131.25 520.93,131.19 520.72,131.15 520.51,131.12 520.3,131.1 520.1,131.1 519.89,131.12 519.68,131.15 519.47,131.19 519.27,131.25 519.08,131.32 518.88,131.4 518.7,131.5 518.52,131.61 518.35,131.74 518.19,131.87 518.04,132.02 517.9,132.17 517.77,132.34 517.66,132.51 517.55,132.69 517.46,132.88 517.38,133.07 517.32,133.27 517.27,133.48 517.23,133.68 517.21,133.89 517.3,134.1 517.31,134.31 517.33,134.52 517.37,134.72 517.42,134.93 517.48,135.13 517.56,135.32 517.65,135.51 517.76,135.69 517.87,135.86 518,136.03 518.14,136.18 518.29,136.33 518.45,136.46 518.62,136.59 518.8,136.7 518.98,136.8 519.18,136.88 519.37,136.95 519.57,137.01 519.78,137.05 519.99,137.08 520.2,137.1 520.4,137.1 520.61,137.08 520.82,137.05 521.03,137.01 521.23,136.95 521.42,136.88 521.62,136.8 521.8,136.7 521.98,136.59 522.15,136.46 522.31,136.33 522.46,136.18 522.6,136.03 522.73,135.86 522.84,135.69 522.95,135.51 523.04,135.32 523.12,135.13 523.18,134.93 523.23,134.72 523.27,134.52 523.29,134.31
GND on Internal Plane 1 (split plane): 1361.31,1159.7 1247,1141.92 1241,1131.92 1247,1121.92 1361.31,1103.29 1361.31,-196.61 -146.91,-196.61 -146.91,1103.3 -32.6,1121.08 -26.6,1131.08 -32.6,1141.08 -146.91,1159.71 -146.91,1280.61 1361.31,1280.61

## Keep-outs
Keep-Out Layer:
  the board outline again, w10

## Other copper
Top Layer:
  region net GND: 652.67,842.28 652.67,862.28 587.67,862.28 587.67,842.28
  region net GND: 767.67,637.28 767.67,717.28 747.67,717.28 747.67,637.28
  region net GND: 862.67,637.28 862.67,697.28 812.67,697.28 812.67,637.28
  pour cut-out: 842.19,1033.15 883.21,1033.15 882.5,1063.56 842.9,1063.56
  pour cut-out: 842.19,1033.15 883.21,1033.15 882.5,1063.56 842.9,1063.56
  pour cut-out: 842.19,1033.15 883.21,1033.15 882.5,1063.56 842.9,1063.56
  text "3858-411(A)" at 3220.9,-2454 h75
  text "Layer 1" at 4185.7,-2454 h75
Mid-Layer 1:
  text "3858-411(A)" at 3220.9,-2654 h75
  text "Layer 3" at 4185.7,-2654 h75
Bottom Layer:
  text "3858-411(A)" at 3220.9,-2754 h75
  text "Layer 4" at 4185.7,-2754 h75
Internal Plane 1 (plane layer: these items are gaps in the copper):
  text "3858-411(A)" at 3220.9,-2554 h75
  text "Layer 2" at 4185.7,-2554 h75

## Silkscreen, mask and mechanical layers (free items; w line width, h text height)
Top Overlay:
  circle w10: c1198.7,759.2 r5.72
  circle w10: c881.8,317.2 r5
  circle w10: c248.3,508.6 r6.96
  circle w10: c590.5,429.2 r0.2
  lines w2: 666.7,311.6 694.7,311.6 694.7,394.3 ; 695.27,311.3 695.27,394 723.27,394 ; 405.77,280.4 488.47,280.4 488.47,308.4 405.77,308.4 405.77,280.4 ; 412.3,187.6 495,187.6 495,215.6 412.3,215.6 412.3,187.6 ; 412.3,220.6 495,220.6 495,248.6 412.3,248.6 412.3,220.6 ; 486.27,319.3 514.27,319.3 514.27,402 486.27,402 486.27,319.3 ; 598.7,27.8 626.7,27.8 626.7,110.5 598.7,110.5 598.7,27.8 ; 628.9,27.8 656.9,27.8 656.9,110.5 628.9,110.5 628.9,27.8 ; 699.3,216.4 782,216.4 782,244.4 699.3,244.4 699.3,216.4 ; 808.3,127.7 836.3,127.7 836.3,210.4 808.3,210.4 808.3,127.7 ; 809.1,232.7 837.1,232.7 837.1,315.4 809.1,315.4 809.1,232.7
  lines w3.1: 880.6,140.6 842.7,140.6 842.7,298.1 880.6,298.1 ; 927.9,140.6 971.7,140.6 971.7,298.1 927.9,298.1 ; 841.9,138.8 971,138.8 971,216.8 971.1,300.2 841.9,300.2 841.9,138.8
  lines w5: 498.2,113.1 498.2,307.7 695.8,307.7 695.8,113.1 498.2,113.1 ; 517.23,133.68 517.21,133.89 517.3,134.1 517.31,134.31 517.33,134.52 517.37,134.72 517.42,134.93 517.48,135.13 517.56,135.32 517.65,135.51 517.76,135.69 517.87,135.86 518,136.03 518.14,136.18 518.29,136.33 518.45,136.46 518.62,136.59 518.8,136.7 518.98,136.8 519.18,136.88 519.37,136.95 519.57,137.01 519.78,137.05 519.99,137.08 520.2,137.1 520.4,137.1 520.61,137.08 520.82,137.05 521.03,137.01 521.23,136.95 521.42,136.88 521.62,136.8 521.8,136.7 521.98,136.59 522.15,136.46 522.31,136.33 522.46,136.18 522.6,136.03 522.73,135.86 522.84,135.69 522.95,135.51 523.04,135.32 523.12,135.13 523.18,134.93 523.23,134.72 523.27,134.52 523.29,134.31 523.2,134.1 523.19,133.89 523.17,133.68 523.13,133.48 523.08,133.27 523.02,133.07 522.94,132.88 522.85,132.69 522.74,132.51 522.63,132.34 522.5,132.17 522.36,132.02 522.21,131.87 522.05,131.74 521.88,131.61 521.7,131.5 521.52,131.4 521.32,131.32 521.13,131.25 520.93,131.19 520.72,131.15 520.51,131.12 520.3,131.1 520.1,131.1 519.89,131.12 519.68,131.15 519.47,131.19 519.27,131.25 519.08,131.32 518.88,131.4 518.7,131.5 518.52,131.61 518.35,131.74 518.19,131.87 518.04,132.02 517.9,132.17 517.77,132.34 517.66,132.51 517.55,132.69 517.46,132.88 517.38,133.07 517.32,133.27 517.27,133.48 517.23,133.68
  lines w10: 350.7,583.73 399.7,583.73
  text "P1" at 1209.67,492 h40
  text "P2" at 27.67,490 h40
  text "RF3858CC1101            3858-411(A)" at 182,-179.9 h60
  text "3858-411(A)" at 3220.9,-2254 h75
  text "Silkscreen Top" at 4185.7,-2254 h75
Bottom Overlay:
  lines w5: -152.3,-207.5 172.7,-207.5 172.7,484 -152.3,484 -152.3,-207.5 ; 1047.7,-207.5 1372.7,-207.5 1372.7,484 1047.7,484 1047.7,-207.5
  lines w12: -122.6,360.5 -116.4,348 -116.4,407.4 ; 1077.4,360.5 1083.6,348 1083.6,407.4
  text "3858-411(A)" at 3220.9,-2954 h75
  text "Silkscreen Bottom" at 4185.7,-2954 h75
Top Paste:
  text "3858-411(A)" at 3220.9,-2154 h75
  text "Paste Mask Top" at 4185.7,-2154 h75
Bottom Paste:
  text "3858-411(A)" at 3220.9,-3054 h75
  text "Paste Mask Bottom" at 4185.7,-3054 h75
Top Solder:
  text "3858-411(A)" at 3220.9,-2354 h75
  text "Soldermask Top" at 4185.7,-2354 h75
Bottom Solder:
  text "3858-411(A)" at 3220.9,-2854 h75
  text "Soldermask Bottom" at 4185.7,-2854 h75
Mechanical 1:
  lines w2: -77.3,423 -52.3,423 -52.3,-187.8 72.7,-187.8 72.7,473 -77.3,473 -77.3,423 ; 510,125 682.8,125 682.8,296.3 510,296.3 510,125 ; 1122.7,423 1147.7,423 1147.7,-187.8 1272.7,-187.8 1272.7,473 1122.7,473 1122.7,423
  text "3858-411(A)" at 3220.9,-3154 h75
  text "Assembly Top" at 4185.7,-3154 h75
Mechanical 2:
  text "Notes for overall board thickness (for internal use only):" at -6264.3,6646 h80
  text "1  Add .0025\" for each outer layer and .0014\" for each inner layer for 1 oz. copper." at -6301.4,6455.11 h80
  text "2  Add .002\" for each outer layer and .0007\" for each inner layer for 0.5 oz. copper." at -6298.4,6241.11 h80
  text "X" at 7530.7,5253 h60
  text "X" at 7430.7,5003 h60
  text "X" at 7130.7,4503 h60
  text "X" at 7830.7,4503 h60
  text "X" at 6430.7,4403 h60
  text "X" at 8230.7,4403 h60
  text "X" at 6680.7,3303 h60
  text "X" at 9430.7,3303 h60
  text "X" at 7280.7,3053 h60
  text "11." at 5182.7,1211 h60
  text "ALL 0.156 DIAMETER HOLES ARE +0.002/-0.001 NON-PLATED." at 5382.7,1211 h60
  text "12." at 5180.7,953 h60
  text "0.0635 HOLE DIAMETER +/-0.002 TOLERANCE." at 5380.7,953 h60
  text "13." at 5180.7,703 h60
  text "0.0635 HOLE TO TOP METAL REGISTRATION +/-0.001 TOLERANCE." at 5380.7,703 h60
  text "14." at 5180.7,453 h60
  text "ALL HOLES ARE TO BE DRILLED WITH THE PRIMARY DRILL, EXCEPT FOR CRITICAL" at 5380.7,453 h60
  text "0.0635 HOLES WHICH MAY BE DRILLED WITH OPTICALLY ALIGNED DRILL MACHINE." at 5380.7,353 h60
  text "15." at 5180.7,103 h60
  text "BOARD FLATNESS SHALL NOT EXCEED 0.005 PER INCH." at 5380.7,103 h60
  text "16." at 5180.7,-147 h60
  text "FIRST ARTICLE INSPECTION OF ALL TOOLING HOLES AND TOP METAL REGISTRATION" at 5380.7,-147 h60
  text "IS REQUIRED." at 5380.7,-247 h60
  text "17." at 5180.7,-497 h60
  text "100% INSPECTION OF TOP METAL TO REFERENCED 0.0635 TOOLING HOLES IS REQUIRED." at 5380.7,-497 h60
  text "18." at 5180.7,-747 h60
  text "ALL DIMENSIONAL INSPECTION DATA WILL BE PROVIDED WITH ORDER." at 5380.7,-747 h60
  text "* MULTIPLE DRILL PROCESS JOBS SEE .DRL, .DR1, .DR2, etc." at -6362.3,-2139 h60
Mechanical 3:
  the board outline again, w10
  text "3858-411(A)" at 3220.9,-3254 h75
  text "Board Outline" at 4185.7,-3254 h75
Mechanical 4:
  drawing of 3692 lines, arcs and shapes, not listed
  text "1" at -5217.24,6882.35 h70
  text "2" at -2392.24,6882.35 h70
  text "3" at 432.76,6882.35 h70
  text "4" at 3257.76,6882.35 h70
  text "5" at 6082.76,6882.35 h70
  text "6" at 8857.76,6882.35 h70
  text "PCB DESIGN" at 4523.83,6658.16 h70
  text "Michael Coolen" at 5538.83,6658.16 h70
  text "PH: 978-670-2246" at 7398.83,6658.16 h70
  text "mcoolen@rfmd.com" at 8783.83,6658.16 h70
  text "CONTACTS" at 3630.76,6569.35 h80
  text "ENGINEERING" at 4526.83,6479.25 h70
  text "Ahmad Abdelmajid" at 5541.83,6479.25 h70
  text "PH: 336-678-7182" at 7401.83,6479.25 h70
  text "AAbdelmajid@rfmd.com" at 8550.83,6479.25 h70
  text "NOTE: SUPPLIER MUST SEND EMAIL TO PCBHOLD@RFMD.COM IN ADDITION TO ABOVE LISTED CONTACTS IF JOB IS PLACED ON HOLD" at 3993.76,6336.35 h55
  text "FABRICATION NOTES:3858-411(A)421(A).zip" at 5180.7,6003 h100
  text "LAYER 1" at -2294.8,5979.5 h50
  text "0.5" at -1829.8,5979.5 h50
  text "OZ BASE COPPER + PLATING" at -1648.8,5979.5 h50
  text ".008" at -6119.8,5842 h50
  text "MATL. TYPE" at -5557.3,5842 h50
  text "FR-4" at -4607.3,5842 h50
  text "Tg 170 DEG C MIN" at -3919.8,5842 h50
  text "LAYER 2" at -2294.8,5704.5 h50
  text "1.0" at -1829.8,5704.5 h50
  text "OZ BASE COPPER" at -1648.8,5704.5 h50
  text "1." at 5180.7,5703 h60
  text "UNLESS OTHERWISE NOTED, BOARD FABRICATION METHODS MUST COMPLY WITH" at 5381.76,5703.35 h60
  text "A" at -6581.24,5607.35 h70
  text "A" at 10213.76,5607.35 h70
  text "RF MICRO DEVICES PCB FABRICATION SPECIFICATION PCB-21-1001." at 5381.76,5603.35 h60
  text ".012" at -6119.8,5567 h50
  text "MATL. TYPE" at -5557.3,5567 h50
  text "FR-4" at -4607.3,5567 h50
  text "Tg 170 DEG C MIN" at -3919.8,5567 h50
  text "A COPY OF PCB-21-1001 CAN BE OBTAINED FROM RF MICRO DEVICES UPON REQUEST." at 5381.76,5503.35 h60
  text "LAYER 3" at -2294.8,5429.5 h50
  text "1.0" at -1829.8,5429.5 h50
  text "OZ BASE COPPER" at -1648.8,5429.5 h50
  text ".008" at -6119.8,5292 h50
  text "MATL. TYPE" at -5557.3,5292 h50
  text "FR-4" at -4607.3,5292 h50
  text "Tg 170 DEG C MIN" at -3919.8,5292 h50
  text "0.034 +/- 10%" at -6257.3,5279.5 h50 r90
  text "2." at 5180.7,5253 h60
  text "ARTWORK FORMAT:" at 5380.7,5253 h60
  text "X" at 6480.7,5253 h60
  text "GERBER 274X" at 6630.7,5253 h60
  text "ODB++" at 7680.7,5253 h60
  text "LAYER 4" at -2294.8,5154.5 h50
  text "0.5" at -1829.8,5154.5 h50
  text "OZ BASE COPPER + PLATING" at -1648.8,5154.5 h50
  text "3." at 5180.7,5003 h60
  text "DELIVER BOARDS AS:" at 5380.7,5003 h60
  text "X" at 6630.7,5003 h60
  text "SINGLES" at 6780.7,5003 h60
  text "PANEL/ARRAY, USE FILE PCBPANEL001(X).ZIP" at 7580.7,5003 h60
  text "(FOR PANELIZED ORDER PCB FABRICATOR SHALL SEND A COPY OF PANELIZED" at 5480.7,4853 h60
  text "GERBER DATA TO CEADS@RFMD.COM)" at 5480.7,4753 h60
  text "4." at 5180.7,4503 h60
  text "SURFACE FINISH:" at 5380.7,4503 h60
  text "X" at 6430.7,4503 h60
  text "ENIG" at 6580.7,4503 h60
  text "HASL" at 7280.7,4503 h60
  text "OSP" at 7980.7,4503 h60
  text "ELECTRO-PLATED HARD GOLD" at 6580.7,4403 h60
  text "ELECTRO-PLATED SOFT GOLD" at 8330.7,4403 h60
  text "5." at 5180.7,4153 h60
  text "SOLDERMASK SHALL BE LIQUID PHOTO-IMAGEABLE, GREEN, GLOSSY." at 5380.7,4153 h60
  text "6." at 5180.7,3903 h60
  text "SILKSCREEN SHALL BE HIGH TEMPERATURE, NON-CONDUCTIVE, WHITE EPOXY BASED INK." at 5380.7,3903 h60
  text "7." at 5180.7,3653 h60
  text "THE PCB SHALL BE MARKED WITH BOTH THE FABRICATOR'S NAME OR LOGO AND" at 5380.7,3653 h60
  text "A DATE CODE SHOWING CALENDAR YEAR AND WEEK (YY/WW)." at 5380.7,3553 h60
  text "8." at 5180.7,3303 h60
  text "100% ELECTRICAL TEST:" at 5380.7,3303 h60
  text "Gerber extracted Netlist" at 6780.7,3303 h60
  text "X" at 8230.7,3303 h60
  text "IPC-D-356 format" at 8430.7,3303 h60
  text "NO E.T." at 9630.7,3303 h60
  text "9." at 5180.7,3053 h60
  text "CONTROLLED IMPEDANCE:" at 5380.7,3053 h60
  text "X" at 6780.7,3053 h60
  text "YES" at 6880.7,3053 h60
  text "NO" at 7480.7,3053 h60
  text "+/-0.001" at 7356.7,2906 h60
  text "0.01425" at 7005.7,2903 h60
  text "REF LAYER" at 8105.7,2903 h60
  text "2" at 8676.7,2903 h60
  text "CPW LAYER" at 5880.7,2893 h60
  text "1" at 6460.7,2893 h60
  text ":" at 6530.7,2893 h60
  text "B" at -6581.24,2857.35 h70
  text "B" at 10213.76,2857.35 h70
  text ":" at 6471.7,2805 h60
  text "+/-5%" at 7452.7,2708 h60
  text "OHMS" at 7183.7,2705 h60
  text "TARGET IMPEDANCE:" at 5480.7,2703 h60
  text "50" at 7005.7,2703 h60
  text "TARGET FREQUENCY:" at 5480.7,2603 h60
  text "2.5GHz to 6GHz" at 7005.7,2603 h60
  text "DIELECTRIC CONSTANT:" at 5480.7,2503 h60
  text "4.26" at 7005.7,2503 h60
  text "*" at 5380.7,2328 h60
  text "DIELECTRIC(S) THAT CAN BE ADJUSTED TO OBTAIN FINISHED THICKNESS:" at 5480.7,2328 h60
  text "LAYER" at 5530.7,2228 h60
  text "2-4" at 5849.7,2227 h60
  text "*" at 5380.7,2053 h60
  text "GERBER DATA SUPPLIED WITH DESIRED FINAL TRACE WIDTHS. PROCESS" at 5480.7,2053 h60
  text "COMPENSATION TRACE WIDTH ADJUSTMENT TO BE DONE BY PCB FABRICATOR." at 5480.7,1953 h60
  text "LAYER" at 8030.7,1704 h60
  text "10." at 5180.7,1703 h60
  text "VIA TYPES/ASSOCIATED LAYERS:" at 5380.7,1703 h60
  text "THRU-HOLE" at 7180.7,1703 h60
  text "1-4" at 8349.7,1703 h60
  text "C" at -6581.24,107.35 h70
  text "C" at 10213.76,107.35 h70
  text "FAMILY P/N:" at 7242.7,-2333 h45
  text "3858" at 7892.7,-2459 h120
  text "D" at -6581.24,-2642.65 h70
  text "D" at 10213.76,-2642.65 h70
  text "TITLE:" at 7242.7,-2683 h45
  text "3858 Evaluation PCB" at 7440.7,-2773 h120
  text "7628 Thorndike Road" at 5742.7,-2828 h80
  text "PCB PART NO:" at 7242.7,-2958 h45
  text "Greensboro, NC 27409" at 5722.7,-2978 h80
  text "3858-411" at 7892.7,-3062.65 h120
  text "Phone: 336-664-1233" at 5712.7,-3128 h80
  text "DOC NO:" at 7242.7,-3278 h45
  text "REV:" at 9742.7,-3278 h45
  text "DATE:" at 5693.76,-3282.65 h45
  text "04/27/11" at 5972.7,-3383 h100
  text "3858-421" at 7902.7,-3389 h120
  text "SIZE:" at 7242.7,-3578.35 h45
  text "SCALE:" at 7679.14,-3578.35 h45
  text "PAGE:" at 8805.2,-3578.35 h45
  text "ALL DIMENSIONS IN INCHES" at 5907.7,-3603 h50
  text "A" at 9744.7,-3613.5 h250
  text "1 OF" at 9092.7,-3683 h100
  text "1" at 9492.7,-3683 h100
  text "B" at 7420.2,-3695.5 h120
  text "DO NOT SCALE" at 7830.2,-3708 h80
  text "UNLESS OTHERWISE SPECIFIED" at 5862.7,-3713 h50
  text "1" at -5217.24,-3917.65 h70
  text "2" at -2392.24,-3917.65 h70
  text "3" at 432.76,-3917.65 h70
  text "4" at 3257.76,-3917.65 h70
  text "5" at 6082.76,-3917.65 h70
  text "6" at 8857.76,-3917.65 h70
  text "ENG/PT PCB ASY DWG REV.1" at -6607.3,-3933 h30
Mechanical 10:
  drawing of 4319 lines, arcs and shapes, not listed
Mechanical 11:
  drawing of 4387 lines, arcs and shapes, not listed
Mechanical 15:
  drawing of 3472 lines, arcs and shapes, not listed
  text "1" at -5217.3,6882 h70
  text "2" at -2392.3,6882 h70
  text "3" at 432.7,6882 h70
  text "4" at 3257.7,6882 h70
  text "5" at 6082.7,6882 h70
  text "6" at 8857.7,6882 h70
  text "PCB DESIGN" at 4523.76,6657.8 h70
  text "Michael Coolen" at 5538.76,6657.8 h70
  text "PH: 978-670-2246" at 7398.76,6657.8 h70
  text "mcoolen@rfmd.com" at 8783.76,6657.8 h70
  text "NOTES :" at -6316.4,6650.11 h80
  text "CONTACTS" at 3630.7,6569 h80
  text "ENGINEERING" at 4526.76,6478.9 h70
  text "Ahmad Abdelmajid" at 5541.76,6478.9 h70
  text "PH: 336-678-7182" at 7401.76,6478.9 h70
  text "AAbdelmajid@rfmd.com" at 8550.76,6478.9 h70
  text "1  WORKMANSHIP & SOLDER PER IPC-A-610C, CLASS 2." at -6301.4,6455.11 h80
  text "2  FOR FURTHER INSTRUCTION ON ASSEMBLY CHECK NOTES ON BILL OF MATERIAL." at -6298.4,6241.11 h80
  text "A" at -6581.3,5607 h70
  text "A" at 10213.7,5607 h70
  text "B" at -6581.3,2857 h70
  text "B" at 10213.7,2857 h70
  text "C" at -6581.3,107 h70
  text "C" at 10213.7,107 h70
  text "FAMILY P/N:" at 7242.64,-2333.35 h45
  text "3858" at 7892.64,-2459.35 h120
  text "D" at -6581.3,-2643 h70
  text "D" at 10213.7,-2643 h70
  text "TITLE:" at 7242.64,-2683.35 h45
  text "3858 Evaluation PCB" at 7440.64,-2773.35 h120
  text "7628 Thor" at 5742.64,-2828.35 h80
  text "ndi" at 6332.64,-2828.35 h80
  text "ke Road" at 6502.64,-2828.35 h80
  text "PCB PART NO:" at 7242.64,-2958.35 h45
  text "Greensboro, NC 27409" at 5722.64,-2978.35 h80
  text "3858-411" at 7892.64,-3063 h120
  text "Phone: 336-664-1233" at 5712.64,-3128.35 h80
  text "DOC NO:" at 7242.64,-3278.35 h45
  text "REV:" at 9742.64,-3278.35 h45
  text "DATE:" at 5693.7,-3283 h45
  text "04/27/11" at 5972.64,-3383.35 h100
  text "3858-471" at 7881.7,-3387 h120
  text "SIZE:" at 7242.64,-3578.71 h45
  text "SCALE:" at 7679.07,-3578.71 h45
  text "PAGE:" at 8805.14,-3578.71 h45
  text "ALL DIMENSIONS IN INCHES" at 5907.64,-3603.35 h50
  text "A" at 9744.64,-3613.85 h250
  text "1 OF" at 9092.64,-3683.35 h100
  text "1" at 9492.64,-3683.35 h100
  text "B" at 7420.14,-3695.85 h120
  text "DO NOT SCALE" at 7830.14,-3708.35 h80
  text "UNLESS OTHERWISE SPECIFIED" at 5862.64,-3713.35 h50
  text "1" at -5217.3,-3918 h70
  text "2" at -2392.3,-3918 h70
  text "3" at 432.7,-3918 h70
  text "4" at 3257.7,-3918 h70
  text "5" at 6082.7,-3918 h70
  text "6" at 8857.7,-3918 h70
  text "ENG/PT PCB FAB DWG REV.1" at -6607.36,-3933.35 h30
Mechanical 16:
  drawing of 3465 lines, arcs and shapes, not listed
  text "6" at -5173.3,6883 h70
  text "5" at -2348.3,6883 h70
  text "4" at 476.7,6883 h70
  text "3" at 3301.7,6883 h70
  text "2" at 6126.7,6883 h70
  text "1" at 8901.7,6883 h70
  text "A" at -6527.3,5608 h70
  text "A" at 10267.7,5608 h70
  text "B" at -6527.3,2858 h70
  text "B" at 10267.7,2858 h70
  text "C" at -6527.3,108 h70
  text "C" at 10267.7,108 h70
  text "FAMILY P/N:" at -3556.24,-2332.35 h45
  text "FAMILY P/N" at -4206.24,-2458.35 h120
  text "D" at -6527.3,-2642 h70
  text "D" at 10267.7,-2642 h70
  text "TITLE:" at -3556.24,-2682.35 h45
  text "DESIGN TITLE" at -4206.24,-2758.35 h120
  text "ke Road" at -2816.24,-2827.35 h80
  text "ndi" at -2646.24,-2827.35 h80
  text "7628 Thor" at -2056.24,-2827.35 h80
  text "PCB PART NO:" at -3556.24,-2957.35 h45
  text "Greensboro, NC 27409" at -2036.24,-2977.35 h80
  text "RFSM3858CC1101X10" at -4206.24,-3062 h120
  text "Phone: 336-664-1233" at -2026.24,-3127.35 h80
  text "REV:" at -6056.24,-3277.35 h45
  text "DOC NO:" at -3556.24,-3277.35 h45
  text "DATE:" at -2007.3,-3282 h45
  text "MM-DD-YY" at -2286.24,-3382.35 h100
  text "RFSM3858CC1101XX" at -4195.3,-3386 h120
  text "PAGE:" at -5118.74,-3577.71 h45
  text "SCALE:" at -3992.67,-3577.71 h45
  text "SIZE:" at -3556.24,-3577.71 h45
  text "ALL DIMENSIONS IN INCHES" at -2221.24,-3602.35 h50
  text "X" at -6146.24,-3607.35 h250
  text "2" at -5806.24,-3682.35 h100
  text "2 OF" at -5406.24,-3682.35 h100
  text "B" at -3733.74,-3694.85 h120
  text "DO NOT SCALE" at -4143.74,-3707.35 h80
  text "UNLESS OTHERWISE SPECIFIED" at -2176.24,-3712.35 h50
  text "6" at -5173.3,-3917 h70
  text "5" at -2348.3,-3917 h70
  text "4" at 476.7,-3917 h70
  text "3" at 3301.7,-3917 h70
  text "2" at 6126.7,-3917 h70
  text "1" at 8901.7,-3917 h70
Drill Drawing:
  text ".Legend" at -6224.3,-1933 h75
  text "3858-411(A)" at 3220.9,-3354 h75
  text "Dimension/Drill" at 4185.7,-3354 h75

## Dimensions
1381.7,1301 to 1381.7,-217 on Drill Drawing
-167.3,1301 to 1381.7,1301 on Drill Drawing
0,0 to -167.3,-217 on Drill Drawing
0,0 to -167.3,-217 on Drill Drawing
